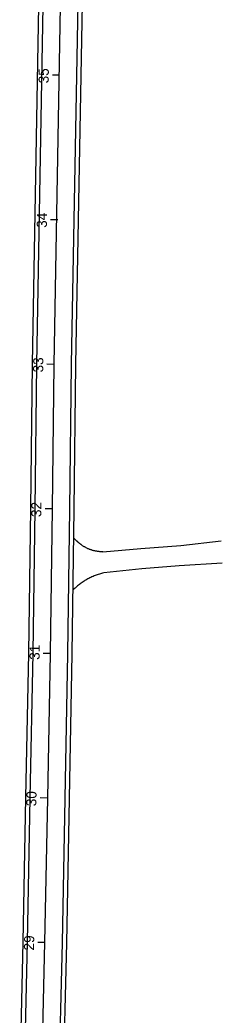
# Model space of a CAD drawing. Extents: x 2318076 to 2324211, y 613525 to 629939.
# Drawn here: x 2318905 to 2319045, y 617785 to 618473 of the extents above; entities that cross this region are included whole.
import ezdxf

# ---------------------------------------------------------------- set-up
doc = ezdxf.new("R2010")
doc.units = 0
for name, color, linetype in [('GE_P_CL_50', 7, 'Continuous'), ('PV_P_EOP', 7, 'Continuous'), ('PV_P_Shoulder', 7, 'Continuous'), ('PV_X_Driveway', 7, 'Continuous')]:
    doc.layers.add(name, color=color, linetype=linetype)

msp = doc.modelspace()

# ---------------------------------------------------------------- linework, layer by layer
at = {"layer": 'GE_P_CL_50'}
for p, q in [((2318932.61, 618435.05), (2318927.61, 618435.11)), ((2318931.36, 618335.06), (2318926.36, 618335.12)), ((2318928.83, 618235.09), (2318923.83, 618235.18)), ((2318927.51, 618135.1), (2318922.51, 618135.14)), ((2318926.34, 618035.11), (2318921.34, 618035.19)), ((2318924.12, 617935.14), (2318919.12, 617935.25)), ((2318922.5, 617835.15), (2318917.5, 617835.24))]:
    msp.add_line(p, q, dxfattribs=at)
msp.add_lwpolyline([(2318920.16, 617734.21), (2318922.5, 617835.15), (2318924.36, 617935.13), (2318926.34, 618035.11), (2318927.67, 618135.1), (2318928.83, 618235.09), (2318934.25, 618535.04)], dxfattribs=at)
at = {"layer": 'PV_P_EOP'}
for points in [[(2318908.16, 617734.48), (2318910.5, 617835.4), (2318912.36, 617935.36), (2318914.34, 618035.31), (2318915.67, 618135.25), (2318916.83, 618235.27), (2318922.25, 618535.27)], [(2318932.16, 617733.94), (2318934.5, 617834.9), (2318936.36, 617934.9), (2318938.34, 618034.91), (2318939.67, 618134.95), (2318940.83, 618234.92), (2318946.25, 618534.81)]]:
    msp.add_lwpolyline(points, dxfattribs=at)
at = {"layer": 'PV_P_Shoulder'}
for points in [[(2318905.16, 617734.55), (2318907.5, 617835.46), (2318909.36, 617935.42), (2318911.34, 618035.36), (2318912.67, 618135.29), (2318913.83, 618235.32), (2318919.25, 618535.32)], [(2318935.16, 617733.87), (2318937.5, 617834.84), (2318939.35, 617934.84), (2318941.34, 618034.86), (2318942.67, 618134.92), (2318943.83, 618234.87), (2318949.25, 618534.75)]]:
    msp.add_lwpolyline(points, dxfattribs=at)
at = {"layer": 'PV_X_Driveway'}
for points in [[(2318947.8, 618110.15), (2318947.68, 618110.24), (2318947.57, 618110.32), (2318947.45, 618110.41), (2318947.34, 618110.49), (2318947.23, 618110.58), (2318947.11, 618110.67), (2318947, 618110.76), (2318946.89, 618110.84), (2318946.77, 618110.93), (2318946.66, 618111.02), (2318946.55, 618111.11), (2318946.44, 618111.2), (2318946.32, 618111.29), (2318946.21, 618111.38), (2318946.1, 618111.47), (2318945.99, 618111.56), (2318945.88, 618111.66), (2318945.77, 618111.75), (2318945.66, 618111.84), (2318945.55, 618111.93), (2318945.44, 618112.03), (2318945.33, 618112.12), (2318945.23, 618112.21), (2318945.12, 618112.31), (2318945.01, 618112.4), (2318944.9, 618112.5), (2318944.8, 618112.6), (2318944.69, 618112.69), (2318944.58, 618112.79), (2318944.48, 618112.88), (2318944.37, 618112.98), (2318944.27, 618113.08), (2318944.16, 618113.18), (2318944.06, 618113.28), (2318943.95, 618113.37), (2318943.85, 618113.47), (2318943.75, 618113.57), (2318943.64, 618113.67), (2318943.54, 618113.77), (2318943.44, 618113.87), (2318943.34, 618113.98), (2318943.23, 618114.08), (2318943.13, 618114.18), (2318943.03, 618114.28), (2318942.93, 618114.38), (2318942.83, 618114.49), (2318942.73, 618114.59), (2318942.63, 618114.69), (2318942.4, 618114.93)], [(2318962.48, 618105.41), (2318962.06, 618105.41), (2318961.63, 618105.42), (2318961.21, 618105.44), (2318960.79, 618105.47), (2318960.37, 618105.5), (2318959.94, 618105.54), (2318959.52, 618105.58), (2318959.1, 618105.64), (2318958.68, 618105.7), (2318958.27, 618105.77), (2318957.85, 618105.84), (2318957.43, 618105.92), (2318957.02, 618106.01), (2318956.61, 618106.11), (2318956.2, 618106.21), (2318955.79, 618106.32), (2318955.38, 618106.44), (2318954.97, 618106.56), (2318954.57, 618106.69), (2318954.17, 618106.83), (2318953.77, 618106.97), (2318953.37, 618107.12), (2318952.98, 618107.28), (2318952.59, 618107.44), (2318952.2, 618107.61), (2318951.82, 618107.79), (2318951.43, 618107.97), (2318951.05, 618108.16), (2318950.68, 618108.36), (2318950.31, 618108.56), (2318949.94, 618108.77), (2318949.57, 618108.98), (2318949.21, 618109.21), (2318948.85, 618109.43), (2318948.5, 618109.67), (2318948.15, 618109.91), (2318947.8, 618110.15)], [(2318962.48, 618105.41), (2318988.75, 618107.73), (2319016.51, 618109.88), (2319044.18, 618112.92)], [(2319044.91, 618097.54), (2319015.14, 618095.82), (2318989.51, 618093.73), (2318963.1, 618090.91)], [(2318963.1, 618090.91), (2318962.34, 618090.72), (2318961.58, 618090.51), (2318960.83, 618090.3), (2318960.08, 618090.07), (2318959.34, 618089.82), (2318958.6, 618089.57), (2318957.86, 618089.3), (2318957.13, 618089.01), (2318956.41, 618088.72), (2318955.69, 618088.41), (2318954.97, 618088.09), (2318954.26, 618087.76), (2318953.56, 618087.42), (2318952.86, 618087.06), (2318952.17, 618086.69), (2318951.49, 618086.31), (2318950.81, 618085.92), (2318950.14, 618085.51), (2318949.47, 618085.1), (2318948.82, 618084.67), (2318948.17, 618084.23), (2318947.52, 618083.78), (2318946.89, 618083.32), (2318946.27, 618082.85), (2318945.65, 618082.37), (2318945.04, 618081.88), (2318944.44, 618081.37), (2318943.85, 618080.86), (2318943.27, 618080.34), (2318942.69, 618079.8), (2318941.93, 618079.06)]]:
    msp.add_lwpolyline(points, dxfattribs=at)

# ---------------------------------------------------------------- texts
at = {"layer": 'GE_P_CL_50'}
for s, rotation, p in [('35', 89.26741, (2318925.04, 618429.39)), ('34', 89.28829, (2318923.79, 618329.48)), ('33', 89.01588, (2318921.23, 618229.44)), ('32', 89.57501, (2318919.97, 618129.46)), ('31', 89.07637, (2318918.77, 618030.69)), ('30', 88.66999, (2318916.49, 617929.44)), ('29', 88.92138, (2318914.9, 617829.67))]:
    msp.add_text(s, height=7, rotation=rotation, dxfattribs=at).set_placement(p)

doc.saveas('drawing.dxf')
